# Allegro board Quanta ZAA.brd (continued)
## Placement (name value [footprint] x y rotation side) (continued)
Q4301  ev@me2n7002dkw-g_115ma  [SC70-2_1-65-6P]  170 113.64 0 top
Q4302  ev@me2n7002dkw-g_115ma  [SC70-2_1-65-6P]  184.97 108.35 180 bottom
Q6059  *2n7002k  [SOT23_213-3_3-2]  149.82 73.78 270 top
Q6060  2n7002k  [SOT23_213-3_3-2]  146.06 73.78 270 top
Q6062  typec@aon7401  [POWER-3_3X3_3-65-5P-SMT]  22.28 111.27 180 top
R1  *short_4  [S0402]  127.95 174.64 315 bottom
R2  *short_4  [S0402]  127.31 174.01 315 bottom
R3  *short_4  [S0402]  126.17 176.42 135 top
R4  *short_4  [S0402]  125.41 175.66 135 top
R5  *tsi@0_4  [R0402]  124.39 178.45 135 top
R6  *tsi@0_4  [R0402]  123.63 177.69 135 top
R7  *tsi@10k_4  [R0402]  134.04 180.61 180 bottom
R8  *tsi@0_4  [R0402]  132.77 180.41 270 bottom
R9  *tsi@10k_4  [R0402]  116.95 175.53 90 top
R10  *tsi@0_4  [R0402]  119.56 177.18 180 top
R11  *short_6  [S0603]  115.5 168.68 90 top
R12  *tsi@10k_4  [R0402]  122.1 175.41 270 top
R13  *tsi@0_4  [R0402]  119.44 173.63 0 top
R14  *short_8  [S0805]  115.7 163.49 270 bottom
R15  *short_8  [S0805]  113.8 162.35 270 bottom
R16  *short_6  [S0603]  115.37 170.71 180 top
R19  *0_4  [R0402]  117.15 170.45 270 top
R28  *short_8  [S0805]  114.43 162.17 270 top
R37  *short_4  [S0402]  113.34 157.25 270 bottom
R38  100k_4  [R0402]  113.72 158.52 0 bottom
R52  10k_4  [R0402]  114.1 151.91 0 top
R53  *100k_4  [R0402]  112.58 152.29 270 top
R58  10k_4  [R0402]  110.8 156.36 0 top
R65  100k_4  [R0402]  114.87 157.75 90 top
R66  *short_4  [S0402]  113.09 157.75 90 top
R67  *short_4  [S0402]  113.98 157.88 90 top
R74  1k_4  [R0402]  98.84 136.65 180 bottom
R85  1k_4  [R0402]  85.53 121.94 90 bottom
R89  60.4/f_4  [R0402]  94.54 126.64 0 bottom
R96  100/f_4  [R0402]  122.05 120.54 180 top
R98  100/f_4  [R0402]  122.23 122.4 270 top
R102  *short_4  [S0402]  90.73 121.94 90 bottom
R103  *0_4  [R0402]  91.75 121.94 90 bottom
R109  100/f_4  [R0402]  132.01 128.16 135 top
R110  *ev@10k_4  [R0402]  154.9 104.08 180 top
R112  *short_6  [S0603]  134.78 129.61 90 bottom
R113  *0_4  [R0402]  185.45 35.4 270 top
R115  iv@1k_4  [R0402]  159.39 105.89 0 top
R119  *short_4  [S0402]  225.48 140.48 90 bottom
R122  100/f_4  [R0402]  130.74 129.43 135 top
R127  ev@100k_4  [R0402]  161.09 105.89 0 top
R130  *10k_4  [R0402]  185.45 37.1 90 top
R131  *0_4  [R0402]  148.27 123.97 180 bottom
R134  54.9/f_4  [R0402]  95.18 131.84 90 bottom
R135  *short_6  [S0603]  133.48 126.18 0 top
R138  100/f_4  [R0402]  94.54 128.67 180 bottom
R145  100/f_4  [R0402]  136.15 124.73 90 top
R148  bl@10k_4  [R0402]  227.13 127.15 0 bottom
R152  2.2k_4  [R0402]  152.33 118.79 180 top
R153  1.5k/f_4  [R0402]  137.68 122.83 180 top
R154  24.9/f_4  [R0402]  118.59 120.6 180 top
R155  100/f_4  [R0402]  95.18 121.18 180 bottom
R156  49.9/f_4  [R0402]  97.85 124.35 180 top
R158  49.9/f_4  [R0402]  102.04 120.03 90 top
R160  *10k_4  [R0402]  140.52 114.8 180 top
R161  100/f_4  [R0402]  96.7 121.56 270 bottom
R162  49.9/f_4  [R0402]  103.03 120.44 90 top
R164  *short_4  [S0402]  151.77 112.8 270 bottom
R165  *2.2k_4  [R0402]  143.39 116.38 180 top
R166  2.2k_4  [R0402]  146.23 114.83 0 top
R167  2.2k_4  [R0402]  146.23 113.94 0 top
R169  *2.2k_4  [R0402]  143.39 115.49 180 top
R171  *short_4  [S0402]  146.36 114.24 0 bottom
R172  gt3@100/f_4  [R0402]  76.51 103.78 180 bottom
R174  200/f_4  [R0402]  143.95 113.94 0 top
R175  *short_4  [S0402]  146.36 115.11 0 bottom
R176  gt3@100/f_4  [R0402]  76.76 108 180 bottom
R177  10k_4  [R0402]  151.42 114.45 270 bottom
R178  113/f_4  [R0402]  141.15 112.97 0 top
R179  *short_6  [S0603]  151.06 112.29 270 top
R180  *short_6  [S0603]  149.03 115.21 180 top
R182  *short_6  [S0603]  149.03 113.68 180 top
R185  *short_6  [S0603]  155.25 112.29 270 top
R186  *short_6  [S0603]  152.46 112.29 270 top
R187  *short_6  [S0603]  148.65 112.26 180 top
R188  *short_6  [S0603]  153.85 112.29 270 top
R190  33_4  [R0402]  171.02 45.59 270 bottom
R192  *short_6  [S0603]  149.15 109.24 180 top
R193  *short_6  [S0603]  146.59 110.33 0 top
R194  *short_4  [S0402]  115.93 108.22 270 top
R195  *1k_4  [R0402]  157.89 112.14 90 top
R198  *short_6  [S0603]  156.65 112.29 270 top
R199  *gc6@10k_4  [R0402]  153.17 105.43 90 top
R203  *typec@0_4  [R0402]  29.01 124.61 90 top
R204  *gc6@10k_4  [R0402]  153.12 104.08 180 top
R205  *150k_4  [R0402]  159.44 102.25 180 top
R206  *typec@0_4  [R0402]  31.68 124.61 90 top
R207  *1k_4  [R0402]  159.44 103.14 0 top
R208  ev@10k_4  [R0402]  159.44 104.16 180 top
R209  *ioac@10k_4  [R0402]  230.31 106.57 90 top
R210  *0_6  [R0603]  165.28 74.39 180 top
R211  10k_4  [R0402]  160.84 98.95 0 top
R212  0_6  [R0603]  165.28 73.02 180 top
R213  75/f_4  [R0402]  19.11 67.33 0 top
R214  100k_4  [R0402]  162.62 88.03 0 bottom
R215  10k_4  [R0402]  153.6 95.9 180 top
R216  *ioac@10k_4  [R0402]  230.31 104.54 270 top
R217  *ioac@33_4  [R0402]  228.28 104.54 270 top
R218  *10k_4  [R0402]  66.16 115.19 180 bottom
R219  75/f_4  [R0402]  19.08 66.34 0 top
R221  *short_8  [S0805]  201.89 188.79 0 bottom
R222  75/f_4  [R0402]  19.08 65.25 0 top
R223  10k_4  [R0402]  153.6 93.87 180 top
R224  *short_4  [S0402]  153.6 92.86 0 top
R227  *10k_4  [R0402]  153.6 91.84 180 top
R228  10k_4  [R0402]  151.69 90.7 0 top
R229  *short_4  [S0402]  153.6 90.7 0 top
R230  *ioac@10k_4  [R0402]  203.89 191.15 0 top
R231  *ioac@100k_4  [R0402]  205.8 191.15 0 top
R234  ev@10k_4  [R0402]  151.69 89.55 0 top
R235  *short_4  [S0402]  153.6 89.55 0 top
R237  *short_8  [S0805]  201.86 191.66 180 bottom
R239  15_4  [R0402]  178.09 50.52 180 top
R240  *short_6  [S0603]  163.12 72.71 90 top
R241  *10k_4  [R0402]  177.73 176.42 180 top
R242  4.7k_4  [R0402]  179.51 176.42 0 top
R243  *0_4  [R0402]  179.89 178.3 90 top
R244  *0_4  [R0402]  179.2 174.64 0 bottom
R245  4.7k_4  [R0402]  178.11 179.72 180 top
R246  *short_8  [S0805]  44.41 67.91 180 top
R247  nac@2.2_8  [R0805]  45.45 64.04 180 top
R248  *ioac@0_8  [R0805]  44.7 65.97 0 top
R249  1m_4  [R0402]  129.85 74.19 90 top
R250  10k_4  [R0402]  137.85 95.27 270 bottom
R251  75/f_8  [R0805]  24.44 88.03 0 top
R252  *short_6  [S0603]  128.71 74.57 90 top
R253  *0_4  [R0402]  177.73 177.82 270 top
R254  *typec@0_4  [R0402]  29.9 114.19 270 top
R255  10m_4  [R0402]  153.47 106.7 90 bottom
R256  *ev@100k_4  [R0402]  156.6 72.97 90 top
R257  *ev@10k_4  [R0402]  155.99 75.18 90 top
R258  *typec@0_4  [R0402]  33.46 114.19 270 top
R259  *ioac@10k_4  [R0402]  50.68 70.38 90 top
R260  *ioac@100k/j_4  [R0402]  49.79 70.38 270 top
R262  75/f_8  [R0805]  24.44 82.32 0 top
R265  *0_4  [R0402]  171.96 90.57 90 bottom
R267  *0_4  [R0402]  173.16 98.44 270 top
R268  *0_4  [R0402]  170.95 90.57 90 bottom
R269  75/f_8  [R0805]  24.44 79.27 0 top
R270  *0_4  [R0402]  204.54 48 180 bottom
R271  *0_6  [R0603]  171.38 98.83 270 top
R272  *0_6  [R0603]  169.22 98.19 0 top
R273  *0_4  [R0402]  169.7 90.6 90 bottom
R274  *0_4  [R0402]  167.67 90.6 90 bottom
R275  *49.9k/f_4  [R0402]  148.52 112.16 270 bottom
R276  *0/j_4  [R0402]  33.2 64.15 90 top
R277  10k/f_4  [R0402]  32.19 64.15 270 top
R278  *0_6  [R0603]  169.22 99.59 180 top
R279  *0_4  [R0402]  168.69 90.6 90 bottom
R280  *49.9k/f_4  [R0402]  146.87 112.16 270 bottom
R281  *10k/f_4  [R0402]  35.87 60.85 270 top
R282  *0_4  [R0402]  166.07 91.43 90 bottom
R283  *49.9k/f_4  [R0402]  149.54 112.16 270 bottom
R289  *0_6  [R0603]  167.82 101.11 0 top
R290  *49.9k/f_4  [R0402]  145.88 112.16 270 bottom
R291  *0_6  [R0603]  166.93 98.95 270 top
R299  20k/f_4  [R0402]  77.4 49.3 180 top
R300  20k/f_4  [R0402]  77.4 50.18 180 top
R301  45.3k/f_4  [R0402]  77.4 51.2 180 top
R303  *120/f_4  [R0402]  14.53 50.82 270 top
R304  1.5k/f_4  [R0402]  79.3 51.2 180 top
R308  1k_4  [R0402]  72.83 51.33 90 top
R312  *120/f_4  [R0402]  14.53 45.49 270 top
R314  *120/f_4  [R0402]  14.53 47.26 270 top
R315  *120/f_4  [R0402]  14.53 49.04 270 top
R316  2.2k_4  [R0402]  17.96 43.33 270 top
R317  2.2k_4  [R0402]  18.98 43.33 270 top
R318  *short_6  [S0603]  218.22 63.01 180 bottom
R319  2.2k_4  [R0402]  18.45 53.36 270 top
R322  2.2k_4  [R0402]  17.48 53.36 270 top
R326  *0_4  [R0402]  224.59 53.87 270 bottom
R329  *short_4  [S0402]  224.8 60.85 0 bottom
R333  *gs@4.7k_4  [R0402]  222.18 62.5 270 bottom
R334  *gs@4.7k_4  [R0402]  224.92 58.95 180 bottom
R336  *short_4  [S0402]  224.8 59.96 0 bottom
R337  *short_4  [S0402]  224.92 57.04 0 bottom
R338  *short_6  [S0603]  213.92 43.94 90 bottom
R339  *short_8  [S0805]  220.35 45.33 90 bottom
R340  *short_4  [S0402]  21.67 34.59 180 top
R341  *short_4  [S0402]  21.67 33.57 180 top
R342  *short_4  [S0402]  21.65 32.4 180 top
R343  *100k_4  [R0402]  205.85 44.17 270 bottom
R344  *0_4  [R0402]  203.51 40.28 270 bottom
R345  *1m_6  [R0603]  207.83 45.69 90 bottom
R348  *short_4  [S0402]  21.65 31.52 180 top
R349  33_4  [R0402]  189.08 44.39 270 bottom
R350  *short_4  [S0402]  203.51 38.12 90 bottom
R351  *0_4  [R0402]  224.08 40.41 180 bottom
R352  22k_4  [R0402]  208.59 39.9 270 bottom
R353  *short_4  [S0402]  21.65 30.37 180 top
R354  10k_4  [R0402]  207.63 38.12 270 bottom
R355  *short_4  [S0402]  21.65 29.48 180 top
R356  10k_4  [R0402]  16.95 22.5 270 top
R359  33_4  [R0402]  205.54 38.12 270 bottom
R360  10k_4  [R0402]  16.06 22.5 270 top
R361  *2.2_6  [R0603]  190.02 41.55 0 bottom
R364  100k_4  [R0402]  16.34 29.18 270 top
R365  *short_4  [S0402]  207.55 37.66 0 top
R366  *0_4  [R0402]  205.87 37.94 270 top
R367  *short_6  [S0603]  200.72 40.53 270 bottom
R368  100k_4  [R0402]  191.32 35.45 270 bottom
R369  *10k_4  [R0402]  198.05 40.81 90 bottom
R370  22_4  [R0402]  202.49 38.12 90 bottom
R371  *short_4  [S0402]  201.61 38.12 90 bottom
R372  1k_4  [R0402]  198.94 40.81 270 bottom
R373  *22_4  [R0402]  189.79 36.98 0 bottom
R374  10k_4  [R0402]  155.89 24.28 0 bottom
R375  *0_4  [R0402]  208.51 36.16 270 top
R376  39k/f_4  [R0402]  21.98 27.71 90 top
R377  20k/f_4  [R0402]  20.96 27.71 270 top
R378  100k_4  [R0402]  209.51 36.16 90 bottom
R380  100k_4  [R0402]  189.79 35 180 bottom
R381  *short_4  [S0402]  18.34 18.43 270 top
R382  ev@10k_4  [R0402]  169.09 29.86 0 bottom
R383  200k_4  [R0402]  209.99 34.74 0 bottom
R384  *short_4  [S0402]  19.36 18.43 270 top
R385  *short_4  [S0402]  19.87 13.86 180 top
R386  *short_4  [S0402]  19.87 13 180 top
R387  *short_4  [S0402]  19.23 10.56 90 top
R388  *short_6  [S0603]  211.51 30.88 0 top
R389  100k_4  [R0402]  189.79 29.86 180 bottom
R390  *10k/f_4  [R0402]  208.84 21.04 0 bottom
R392  *short_4  [S0402]  18.34 10.56 90 top
R393  *0_4  [R0402]  208.51 36.16 270 bottom
R394  *0_4  [R0402]  211.51 33.19 180 top
R395  *29.4k/f_4  [R0402]  208.84 22.02 0 bottom
R397  100k_4  [R0402]  208.57 28.39 0 bottom
R399  *0_4  [R0402]  209.23 26.18 180 bottom
R400  *0_4  [R0402]  206.84 31.34 0 top
R401  *0_4  [R0402]  210.32 28.75 0 bottom
R402  *short_4  [S0402]  121.79 23.16 270 bottom
R403  *short_4  [S0402]  137.85 16.53 0 bottom
R404  *short_6  [S0603]  72.95 15.13 90 top
R405  *short_4  [S0402]  141.38 15.08 0 bottom
R406  *short_6  [S0603]  74.22 15.13 90 top
R407  2.2k_4  [R0402]  205.49 15.13 180 bottom
R408  *short_4  [S0402]  207.32 15.13 180 bottom
R409  *2.2k_4  [R0402]  141.38 14.14 180 bottom
R410  *2.2k_4  [R0402]  136.07 16.78 0 bottom
R411  *short_4  [S0402]  119.66 21.36 90 bottom
R412  *short_4  [S0402]  120.93 21.36 90 bottom
R414  *short_6  [S0603]  75.49 15.13 90 top
R415  10k_4  [R0402]  119.63 23.16 90 bottom
R416  10k_4  [R0402]  120.9 23.16 90 bottom
R417  *10k_4  [R0402]  205.37 10.59 0 bottom
R418  4.7k_4  [R0402]  204.5 19.22 270 bottom
R419  *short_6  [S0603]  76.76 15.13 90 top
R420  62/f_4  [R0402]  207.07 10.59 0 bottom
R421  4.7k_4  [R0402]  208.39 18.56 270 bottom
R422  62/f_4  [R0402]  207.07 11.7 0 bottom
R423  *10k_4  [R0402]  205.37 11.7 0 bottom
R424  2.2k_4  [R0402]  205.49 13.61 180 bottom
R425  *short_4  [S0402]  207.32 13.61 180 bottom
R426  *1m_4  [R0402]  53.04 20.75 270 top
R427  *1m_4  [R0402]  55.2 20.75 270 top
R428  *1m_4  [R0402]  58.62 20.73 270 top
R429  *1m_4  [R0402]  59.72 20.73 270 top
R430  47/f_4  [R0402]  58.62 18.83 90 top
R431  124/f_4  [R0402]  59.72 18.83 90 top
R432  47/f_4  [R0402]  54.1 18.84 90 top
R433  124/f_4  [R0402]  55.2 18.84 90 top
R435  *100k_4  [R0402]  79.69 9.77 270 top
R436  *1m_4  [R0402]  54.1 20.75 270 top
R437  *short_4  [S0402]  57.53 18.95 270 top
R438  *short_4  [S0402]  53.04 18.84 270 top
R439  *0_4  [R0402]  57.53 17.05 90 top
R440  *0_4  [R0402]  53.04 17.06 90 top
R441  33_4  [R0402]  131.88 178.84 0 bottom
R442  *short_4  [S0402]  128.2 178.84 0 top
R443  *tsi@0_4  [R0402]  131.76 180.41 270 bottom
R444  *tsi@10k_4  [R0402]  121.09 168.55 90 bottom
R447  *100k_4  [R0402]  122.79 169.91 0 bottom
R448  *100k_4  [R0402]  122.76 168.9 180 bottom
R449  *100k_4  [R0402]  124.52 168.93 0 bottom
R450  *100k_4  [R0402]  124.52 169.95 180 bottom
R457  33_4  [R0402]  121.85 171.85 0 top
R460  33_4  [R0402]  182.63 47.82 270 bottom
R463  100k_4  [R0402]  169.09 30.75 0 bottom
R465  1k_4  [R0402]  94.54 125.62 0 bottom
R478  *0_4  [R0402]  99.35 138.42 90 bottom
R485  10k_4  [R0402]  98.41 138.42 90 bottom
R488  *1k_4  [R0402]  98.99 134.11 0 bottom
R512  2.7k/f_4  [R0402]  118.27 127.4 270 bottom
R513  *1k_4  [R0402]  101.28 131.85 270 bottom
R514  51_4  [R0402]  103.46 131.85 90 bottom
R515  51_4  [R0402]  104.48 131.85 90 bottom
R529  1k_4  [R0402]  99.24 131.85 90 bottom
R530  100/f_4  [R0402]  100.26 129.81 90 bottom
R531  499/f_4  [R0402]  96.32 125.62 180 bottom
R532  *100k_4  [R0402]  96.95 129.43 0 bottom
R533  *100k_4  [R0402]  98.85 129.43 0 bottom
R534  51_4  [R0402]  105.34 129.81 90 bottom
R536  1m_4  [R0402]  117.79 130.83 180 bottom
R537  *51_4  [R0402]  106.99 129.81 90 bottom
R540  10k_4  [R0402]  147.76 125.11 180 bottom
R541  10k_4  [R0402]  147.76 127.02 180 bottom
R542  10k_4  [R0402]  147.76 126 180 bottom
R543  10k_4  [R0402]  147.76 127.91 180 bottom
R544  *10k_4  [R0402]  95.31 124.61 180 bottom
R546  *0_4  [R0402]  108.9 131.46 90 bottom
R548  1k_4  [R0402]  95.43 123.72 180 bottom
R550  *short_6  [S0603]  134.04 129 0 top
R552  220_4  [R0402]  95.18 130.08 270 bottom
R553  *0_4  [R0402]  109.78 131.46 90 bottom
R554  10k_4  [R0402]  96.83 124.23 90 bottom
R555  10k_4  [R0402]  146.36 123.97 180 bottom
R556  *short_4  [S0402]  148.27 122.96 0 bottom
R558  51_4  [R0402]  101.28 129.81 90 bottom
R559  51_4  [R0402]  102.29 131.85 90 bottom
R560  *short_4  [S0402]  181.57 37.87 180 top
R561  10k_4  [R0402]  145.85 122.7 0 bottom
R562  100/f_4  [R0402]  138.39 121.32 90 top
R563  100k_4  [R0402]  147.73 120.59 270 top
R564  100k_4  [R0402]  145.47 118.89 180 top
R565  gt3@0_6  [R0603]  90.65 125.16 270 bottom
R568  10k_4  [R0402]  149.13 121.79 0 bottom
R569  *10k_4  [R0402]  147.55 120.16 180 bottom
R570  100k_4  [R0402]  149.97 119.83 270 bottom
R571  *short_4  [S0402]  150.55 119.65 0 top
R572  2.2k_4  [R0402]  157.92 116.61 270 top
R573  *10k_4  [R0402]  144.71 120.16 180 bottom
R574  *10k_4  [R0402]  144.71 119.15 180 bottom
R575  *10k_4  [R0402]  146.61 119.15 0 bottom
R576  2.2k_4  [R0402]  157.92 118.76 90 top
R577  *2.2k_4  [R0402]  152.33 117.49 180 top
R578  2.2k_4  [R0402]  140.52 115.64 0 top
R580  2.2k_4  [R0402]  140.52 116.66 0 top
R582  2.2k_4  [R0402]  150.53 117.42 180 top
R585  2.2k_4  [R0402]  149.71 114.45 90 bottom
R586  *1k_4  [R0402]  150.55 114.45 90 bottom
R587  1k_4  [R0402]  144.58 109.8 0 bottom
R588  15_4  [R0402]  179.51 56.79 270 top
R589  15_4  [R0402]  180.9 58.57 90 top
R590  *tpm@10k_4  [R0402]  148.52 105.56 180 bottom
R591  10k_4  [R0402]  178.24 56.79 270 top
R592  10k_4  [R0402]  146.79 105.56 180 bottom
R593  10k_4  [R0402]  152.58 107.97 180 top
R595  10k_4  [R0402]  148.65 104.92 0 top
R598  nac@10k_4  [R0402]  148.65 105.94 0 top
R599  *ioac@10k_4  [R0402]  150.68 105.94 180 top
R600  *10k_4  [R0402]  150.68 104.92 180 top
R601  2.2k_4  [R0402]  13.14 81.91 180 bottom
R602  *short_4  [S0402]  178.24 58.54 270 top
R605  10k_4  [R0402]  150.68 105.05 180 bottom
R606  *10k_4  [R0402]  148.65 107.97 180 top
R607  10k_4  [R0402]  150.42 107.97 180 top
R608  *gs@10k_4  [R0402]  152.58 105.05 180 bottom
R609  10k_4  [R0402]  66.9 120.08 0 bottom
R610  *10k_4  [R0402]  147 102.89 180 bottom
R611  *10k_4  [R0402]  148.9 102.89 180 bottom
R612  *10k_4  [R0402]  147 103.86 180 bottom
R613  *10k_4  [R0402]  148.9 103.91 180 bottom
R614  *10k_4  [R0402]  150.55 102.38 270 bottom
R615  *10k_4  [R0402]  152.08 102.76 180 bottom
R616  200/f_4  [R0402]  148.9 101.87 0 bottom
R617  *typec@4.7k/f_4  [R0402]  27.79 121.98 0 bottom
R618  *10k_4  [R0402]  152.08 100.35 180 bottom
R619  *1k_4  [R0402]  152.08 101.75 0 bottom
R620  2.2k_4  [R0402]  12.76 76.6 180 bottom
R621  *10k_4  [R0402]  95.05 101.87 90 bottom
R623  22_4  [R0402]  152.08 98.17 0 bottom
R624  *20k_4  [R0402]  150.17 100.35 0 bottom
R625  *1k_4  [R0402]  152.08 99.33 0 bottom
R626  22_4  [R0402]  152.08 95.78 270 bottom
R627  22_4  [R0402]  152.58 97.17 0 bottom
R628  8.2k/f_4  [R0402]  160.64 72.46 270 top
R629  10k_4  [R0402]  153.22 90.32 270 bottom
R630  8.2k/f_4  [R0402]  142.55 97.68 0 bottom
R631  *10k_4  [R0402]  152.2 90.32 90 bottom
R632  gt3@0_4  [R0402]  78.42 106.45 180 bottom
R633  gt3@0_4  [R0402]  78.42 105.05 180 bottom
R634  gt3@0_4  [R0402]  76.51 105.05 0 bottom
R635  49.9/f_4  [R0402]  158.88 73.58 270 top
R636  gt3@0_4  [R0402]  76.51 106.45 0 bottom
R639  10k_4  [R0402]  139.5 95.4 270 bottom
R640  *short_4  [S0402]  139.86 97.17 0 bottom
R642  10k_4  [R0402]  134.93 93.24 90 bottom
R643  *0_4  [R0402]  132.9 95.14 270 bottom
R644  33_4  [R0402]  129.6 95.14 270 bottom
R645  33_4  [R0402]  130.61 93.24 270 bottom
R646  49.9/f_4  [R0402]  157.92 73.56 270 top
R647  *short_4  [S0402]  133.91 95.14 90 bottom
R648  10k_4  [R0402]  133.91 93.24 90 bottom
R649  1k_4  [R0402]  180.9 56.79 270 top
R650  15_4  [R0402]  179.51 58.57 90 top
R651  8.2k/f_4  [R0402]  136.84 95.27 90 bottom
R652  *short_4  [S0402]  139.5 93.24 270 bottom
R653  *short_4  [S0402]  141.15 93.24 270 bottom
R654  15_4  [R0402]  182.17 51.96 90 top
R655  *short_4  [S0402]  135.82 93.24 270 bottom
R657  *short_8  [S0805]  225.56 105.23 0 bottom
R659  *short_4  [S0402]  140.52 95.4 270 bottom
R660  33_4  [R0402]  132.26 93.24 270 bottom
R661  *short_4  [S0402]  135.06 95.14 270 bottom
R667  33_4  [R0402]  131.63 95.14 270 bottom
R668  *short_4  [S0402]  141.66 95.4 270 bottom
R670  *short_4  [S0402]  130.89 100.65 180 top
R671  nac@0_4  [R0402]  201.1 181.12 0 bottom
R672  nac@0_8  [R0805]  226.22 102.69 90 bottom
R673  *ioac@22_8  [R0805]  222.81 105.04 270 bottom
R676  *short_4  [S0402]  137.34 93.24 270 bottom
R677  *short_4  [S0402]  138.49 93.24 270 bottom
R678  80.6/f_4  [R0402]  130.36 103.35 270 top
R679  470_4  [R0402]  130.89 101.65 180 top
R680  *ioac@0_4  [R0402]  201.1 180.11 0 bottom
R681  100/f_4  [R0402]  131.3 103.35 270 top
R682  *100k_4  [R0402]  89.59 102 270 bottom
R683  *0_6  [R0603]  154.16 73.76 180 top
R684  15_4  [R0402]  180.9 50.18 90 top
R685  121/f_4  [R0402]  130.49 106.14 90 top
R686  *ioac@100k  [R0402]  225.18 110.09 270 top
R687  15_4  [R0402]  180.9 51.96 90 top
R688  *short_4  [S0402]  201.07 177.03 0 bottom
R690  *short_4  [S0402]  201.07 176.09 0 bottom
R691  15_4  [R0402]  183.5 51.96 270 top
R692  *ioac@100k  [R0402]  225.23 107.08 180 top
R693  *short_4  [S0402]  201.07 175.15 0 bottom
R694  *0_4  [R0402]  201.05 172.82 180 bottom
R695  *ioac@100k  [R0402]  227.77 108.48 90 bottom
R696  *short_4  [S0402]  201.07 174.19 0 bottom
R697  *gt3@10k_4  [R0402]  48.44 83.46 0 top
R698  1k_4  [R0402]  179.89 51.96 270 top
R699  *0_4  [R0402]  201.05 171.83 180 bottom
R702  *ioac@1k_4  [R0402]  43.24 80.92 90 top
R703  *ioac@0_4  [R0402]  225.23 104.92 180 top
R704  *ioac@0_4  [R0402]  225.23 105.94 180 top
R705  gt3@10k_4  [R0402]  48.44 81.55 0 top
R706  *gt3@10k_4  [R0402]  48.42 81.55 180 bottom
R707  gt3@10k_4  [R0402]  48.42 82.44 180 bottom
R708  *gt3@10k_4  [R0402]  48.44 82.44 0 top
R709  nac@0/j_4  [R0402]  43.24 79.01 90 top
R710  *ioac@10k_4  [R0402]  205.8 189.22 180 top
R712  *ioac@100k_4  [R0402]  203.89 189.22 180 top
R713  nac@0_4  [R0402]  46.97 77.26 90 top
R714  *10k_4  [R0402]  201.1 182.14 180 bottom
R715  *ioac@0_4  [R0402]  46.11 77.26 90 top
R716  *10k_4  [R0402]  202.49 185.57 180 bottom
R717  *10k_4  [R0402]  218.88 72.54 270 top
R718  *short_4  [S0402]  26.09 53.87 270 top
R719  100k_4  [R0402]  219.51 69.11 0 top
R720  20k_4  [R0402]  15.68 58.44 0 top
R721  *short_4  [S0402]  15.68 57.17 0 top
R722  *1m_4  [R0402]  26.98 53.87 270 top
R725  *short_6  [S0603]  168.51 65.12 180 bottom
R729  *tpm@10k_4  [R0402]  166.55 67.33 270 bottom
R730  10k_4  [R0402]  177.32 47.87 90 bottom
R731  4.7k_4  [R0402]  178.26 45.64 270 bottom
R732  4.7k_4  [R0402]  179.2 45.64 270 bottom
R733  2.2k_4  [R0402]  181.16 45.61 270 bottom
R734  2.2k_4  [R0402]  182.17 45.61 270 bottom
R735  *10k_4  [R0402]  173.92 45.61 270 bottom
R736  *10k_4  [R0402]  173.92 47.87 90 bottom
R737  1k_4  [R0402]  130.61 95.14 270 bottom
R738  43_4  [R0402]  180.3 48.15 180 bottom
R739  100k_4  [R0402]  181.79 47.82 270 bottom
R740  ev@10k_4  [R0402]  167.19 29.89 180 bottom
R741  10k_4  [R0402]  172.22 48 270 bottom
R742  *short_4  [S0402]  164.14 76.7 90 bottom
R743  *short_4  [S0402]  162.03 72.08 90 bottom
R744  *tpm@4.7k_4  [R0402]  170.21 72.46 0 bottom
R745  *short_6  [S0603]  163.25 66.57 270 bottom
R746  33_4  [R0402]  170.9 42.92 90 bottom
R747  2.2_6  [R0603]  187.89 47.44 0 bottom
R749  *short_4  [S0402]  189.79 33.93 180 bottom
R750  *short_4  [S0402]  209.33 24.58 180 bottom
R751  33_4  [R0402]  190.58 27.99 0 bottom
R752  0_6  [R0603]  130.45 14.62 270 bottom
R753  *10k_4  [R0402]  217.1 37.13 270 bottom
R754  *0_4  [R0402]  130.99 16.91 90 bottom
R756  *0_4  [R0402]  219.89 70.76 90 top
R757  *0_4  [R0402]  218.88 70.76 90 top
R759  *short_4  [S0402]  148.88 101.87 180 top
R760  *short_4  [S0402]  93.15 100.35 0 bottom
R761  100k_4  [R0402]  94.54 127.65 0 bottom
R762  gt3@0_4  [R0402]  78.42 103.78 0 bottom
R764  10k_4  [R0402]  148.65 106.95 180 top
R765  *10k_4  [R0402]  150.68 106.95 180 top
R766  ev_sp@10k_4  [R0402]  150.68 104.16 180 bottom
R767  ev_a@10k_4  [R0402]  152.58 104.16 180 bottom
R774  33_4  [R0402]  171.63 27.2 90 bottom
R775  *0_4  [R0402]  151.06 115.11 180 top
R776  for15@33_4  [R0402]  150.55 19.58 270 bottom
R777  *0_4  [R0402]  89.72 121.94 270 bottom
R778  1k_4  [R0402]  142.42 110.38 180 top
R779  2.2_6  [R0603]  190.02 40.15 0 bottom
R781  20k/f_4  [R0402]  152.33 119.78 180 top
R782  *short_4  [S0402]  189.79 30.88 180 bottom
R783  *0_4  [R0402]  168.92 35.3 90 bottom
R784  *0_4  [R0402]  189.97 43.68 270 bottom
R785  *0_4  [R0402]  175.11 45.61 270 bottom
R786  100k_4  [R0402]  152.25 72.84 90 top
R788  49.9/f_4  [R0402]  100.26 131.85 90 bottom
R789  *short_6  [S0603]  154.16 75.2 0 top
R790  *short_4  [S0402]  172.47 52.39 90 bottom
R791  *short_4  [S0402]  189.01 27.4 270 bottom
R792  *short_4  [S0402]  160.08 32.02 90 bottom
R795  *short_4  [S0402]  102.29 129.81 90 bottom
R796  *short_4  [S0402]  104.32 129.81 90 bottom
R797  *short_4  [S0402]  103.31 129.81 90 bottom
R816  *short_4  [S0402]  18.22 123.46 0 bottom
R817  *short_4  [S0402]  18.22 122.7 0 bottom
R818  *short_4  [S0402]  19.21 118.66 0 top
R819  *short_4  [S0402]  19.21 119.48 0 top
R820  *short_4  [S0402]  16.34 117.6 0 bottom
R821  *short_4  [S0402]  16.34 116.71 0 bottom
R856  ev@10k_4  [R0402]  198.43 109.88 180 bottom
R857  *ev@0_4  [R0402]  197.29 111.78 90 bottom
R858  *ev@0_4  [R0402]  196.27 111.78 90 bottom
R859  ev@40.2/f_4  [R0402]  188.4 140.1 180 top
R860  ev@40.2/f_4  [R0402]  190.25 140.1 0 top
R861  ev@60.4/f_4  [R0402]  189.92 137.18 270 top
R866  *fpd@0_4  [R0402]  111.31 35.2 90 top
R948  *short_8  [S0805]  179.71 88.72 90 bottom
R956  *short_4  [S0402]  166.43 93.36 90 bottom
R957  *10k_4  [R0402]  165.41 93.36 270 bottom
R958  *short_4  [S0402]  167.95 105.81 270 bottom
R959  *short_4  [S0402]  166.93 105.81 270 bottom
R960  *short_4  [S0402]  163.51 91.16 0 bottom
R961  1m_4  [R0402]  171.25 106.06 270 bottom
R968  *0_4  [R0402]  170.24 106.06 90 bottom
R1297  ev_b@931/f_4  [R0402]  215.58 153.82 90 bottom
R1308  ev_b@10k_4  [R0402]  213.49 129.76 180 top
R1309  ev_b@10k_4  [R0402]  214.94 138.83 90 top
R1318  ev_b@10k_4  [R0402]  211.64 129.76 0 top
R1319  ev_b@10k_4  [R0402]  211.89 137.56 90 top
R1323  ev_b@1k_4  [R0402]  213.8 122.32 0 top
R1330  ev_b@931/f_4  [R0402]  216.97 112.41 270 bottom
R1331  ev_b@549/f_4  [R0402]  215.83 112.41 270 bottom
R1333  ev_b@120/f_4  [R0402]  211.51 153.82 90 bottom
R1335  ev_b@120/f_4  [R0402]  212.4 112.41 270 bottom
R1336  ev_b@80.6/f_4  [R0402]  212.38 121.41 0 top
R1337  ev_b@1.33k/f_4  [R0402]  214.69 112.41 270 bottom
R1342  ev_b@80.6/f_4  [R0402]  212.93 149.78 180 top
R1367  ev_b@1.33k/f_4  [R0402]  213.67 153.82 90 bottom
R1381  ev_b@549/f_4  [R0402]  214.56 153.82 90 bottom
R1410  ev_a@931/f_4  [R0402]  206.43 164.1 90 bottom
R1415  ev_a@120/f_4  [R0402]  205.54 160.42 0 bottom
R1416  ev_a@1.33k/f_4  [R0402]  205.54 162.45 0 bottom
R1417  ev_a@549/f_4  [R0402]  205.37 164.1 90 bottom
R1426  ev_a@80.6/f_4  [R0402]  195.89 160.8 90 top
R1438  ev_a@1k_4  [R0402]  173.03 160.42 270 top
R1466  ev_a@10k_4  [R0402]  190.3 162.96 270 top
R1467  ev_a@10k_4  [R0402]  189.41 162.96 270 top
R1472  ev_a@10k_4  [R0402]  180.4 160.93 270 top
R1473  ev_a@10k_4  [R0402]  175.44 160.8 270 top
R1500  ev_a@80.6/f_4  [R0402]  169.35 161.31 270 top
R1508  ev_a@1.33k/f_4  [R0402]  165.16 162.96 180 top
R1509  ev_a@549/f_4  [R0402]  165.16 163.98 180 top
R1510  ev_a@120/f_4  [R0402]  165.16 160.93 180 top
R1513  ev_a@931/f_4  [R0402]  165.16 164.99 180 top
R2854  *fpd@10k_4  [R0402]  114.94 32.13 90 top
R2855  *short_4  [S0402]  112.83 18.94 90 bottom
R2868  fpd@10_4  [R0402]  112.83 22.88 0 bottom
R2870  *short_4  [S0402]  112.83 26.44 0 bottom
R2872  *short_4  [S0402]  112.83 21.99 0 bottom
R4000  gc6@10k_4  [R0402]  164.27 110.89 90 top
R4001  gc6@10k_4  [R0402]  164.03 108.56 90 top
R4002  gc6@100k_4  [R0402]  165.26 110.89 270 top
R4003  *gc6@0_8  [R0805]  173.34 108.3 90 top
R4004  *gc6@10k_4  [R0402]  220.54 107.96 270 bottom
R4005  gc6@100k_4  [R0402]  219.53 107.96 90 bottom
R4006  *ev@200/f_4  [R0402]  164.51 143.28 0 bottom
R4007  *gc6@0_4  [R0402]  217.1 108.58 0 bottom
R4008  ev@10k_4  [R0402]  170.88 126.77 180 top
R4009  ev@2.49k/f_4  [R0402]  164.53 144.29 180 bottom
R4010  *short_6  [S0603]  171.51 140.76 180 top
R4011  ev@10k_4  [R0402]  169.3 125.93 0 top
R4012  gc6@1m_4  [R0402]  229.55 115.34 180 bottom
R4100  *ev@60.4/f_4  [R0402]  192.46 127.53 0 top
R4102  *ev@60.4/f_4  [R0402]  192.59 134.89 0 top
R4103  *ev@60.4/f_4  [R0402]  184.71 143.53 90 top
R4105  *ev@60.4/f_4  [R0402]  178.11 145.94 0 top
R4200  ev@1.5k/f_4  [R0402]  177.73 110.51 270 bottom
R4201  ev@4.7k_4  [R0402]  176.21 108.6 270 bottom
R4202  *ev@100k/f_4  [R0402]  178.75 110.51 90 bottom
R4203  ev@4.7k_4  [R0402]  174.81 110.51 270 bottom
R4204  ev@4.7k_4  [R0402]  157.13 139.29 90 bottom
R4205  ev@4.7k_4  [R0402]  159.42 142.46 90 bottom
R4206  ev@100k/f_4  [R0402]  158.12 139.29 270 bottom
R4207  ev@4.7k_4  [R0402]  164.27 142.13 180 bottom
R4208  ev@1.8k/f_4  [R0402]  182.43 114.19 270 bottom
R4209  ev@1.8k/f_4  [R0402]  182.94 119.78 270 top
R4210  *ev@10k_4  [R0402]  187.89 109.75 270 top
R4211  ev@10k_4  [R0402]  187.89 111.78 90 top
R4212  ev@10k_4  [R0402]  191.12 111.78 270 bottom
R4300  ev@49.9k/f_4  [R0402]  192.24 109.71 90 bottom
R4301  *ev@45.3k/f_4  [R0402]  197.29 109.75 90 top
R4302  *ev@15k/f_4  [R0402]  196.27 109.75 90 top
R4303  *ev@34.8k/f_4  [R0402]  188.91 109.75 90 top
R4304  *ev@20k/f_4  [R0402]  188.91 109.75 90 bottom
R4305  ev_sp@xxxx  [R0402]  195.92 109.04 90 bottom
R4306  ev_sp@4.99k/f_4  [R0402]  198.3 109.75 90 top
R4307  *ev@10k/f_4  [R0402]  189.92 109.75 90 top
R4308  *ev@4.99k/f_4  [R0402]  191.27 109.71 270 bottom
R4309  *ev@4.99k/f_4  [R0402]  197.29 111.78 90 top
R4310  *ev@24.9k/f_4  [R0402]  196.27 111.78 90 top
R4311  *ev@4.99k/f_4  [R0402]  188.91 111.78 90 top
R4312  *ev@45.3k/f_4  [R0402]  188.91 111.78 90 bottom
R4313  ev_sp@xxxx  [R0402]  194.98 109.04 270 bottom
R4314  ev_sp@4.99k/f_4  [R0402]  198.3 111.78 90 top
R4315  ev@4.99k/f_4  [R0402]  189.92 111.78 90 top
R4316  ev@10k_4  [R0402]  186.49 114.19 270 bottom
R4317  ev@10k_4  [R0402]  185.48 114.19 270 bottom
R4318  ev@10k_4  [R0402]  183.44 114.32 90 top
R4319  ev@10k_4  [R0402]  166.6 114.09 0 top
R4320  *ev@10k_4  [R0402]  187 111.78 90 top
R4321  ev@10k_4  [R0402]  188.91 114.19 90 bottom
R4322  ev@10k_4  [R0402]  183.44 114.19 90 bottom
R4323  *ev@10k_4  [R0402]  187.38 111.14 0 bottom
R4324  ev@10k_4  [R0402]  183.44 112.16 90 top
R4325  ev@100k_4  [R0402]  187.38 112.16 0 bottom
R4326  ev@10k_4  [R0402]  189.62 105.25 180 bottom
R4328  *short_4  [S0402]  193.15 105.25 180 bottom
R4329  *short_4  [S0402]  191.37 105.25 180 bottom
R4330  *ev@10k_4  [R0402]  162.36 124.99 180 bottom
R4331  *ev@10k_4  [R0402]  162.36 126.26 180 bottom
R4332  *ev@10k_4  [R0402]  162.39 122.8 180 bottom
R4334  ev@10k_4  [R0402]  162.39 123.82 180 bottom
R4335  *short_4  [S0402]  189.01 107.16 0 bottom
R4336  *short_4  [S0402]  194.6 106.06 270 bottom
R4337  ev@1.8k/f_4  [R0402]  184.46 114.19 90 bottom
R4338  ev@1.8k/f_4  [R0402]  182.94 122.07 270 top
R4339  ev@1.8k/f_4  [R0402]  182.43 111.91 90 bottom
R4340  ev@1.8k/f_4  [R0402]  181.41 111.91 90 bottom
R4341  ev@2.2k_4  [R0402]  185.58 110.46 270 bottom
R4342  ev@2.2k_4  [R0402]  182.3 108.1 270 bottom
R4343  *ev@10k_4  [R0402]  187.89 114.19 90 bottom
R4344  *ev@10k_4  [R0402]  189.92 109.75 270 bottom
R4345  ev@40.2k/f_4  [R0402]  189.92 111.78 90 bottom
R4346  *ev@0_4  [R0402]  166.62 115.19 180 top
R10842  *short_4  [S0402]  113.09 127.79 270 bottom
R10843  *short_4  [S0402]  112.2 127.79 270 bottom
R10844  *short_4  [S0402]  110.04 127.79 270 bottom
R10845  *short_4  [S0402]  110.93 127.79 270 bottom
R10846  *short_4  [S0402]  147.26 118.89 180 top
R10847  *short_4  [S0402]  98.25 130.83 270 bottom
R10848  *short_4  [S0402]  97.24 130.83 270 bottom
R10871  240_4  [R0402]  102.04 51.58 90 top
R10872  *10k_4  [R0402]  145.85 39.16 90 bottom
R10873  24.9/f_4  [R0402]  128.2 40.2 90 top
R10875  240_4  [R0402]  104.45 47.14 180 top
R10877  10k_4  [R0402]  127.82 47.14 90 top
R10878  2/f_6  [R0603]  126.29 38.12 0 top
R10879  240_4  [R0402]  104.45 43.71 180 top
R10880  *10k_4  [R0402]  147 39.16 90 bottom
R10881  240_4  [R0402]  104.45 51.96 180 top
R10882  10k_4  [R0402]  145.85 37.38 90 bottom
R10883  1k/f_4  [R0402]  125.91 42.82 0 top
R10884  240_4  [R0402]  103.05 51.58 90 top
R10885  240_4  [R0402]  116.64 42.95 180 top
R10886  10k_4  [R0402]  147 37.38 90 bottom
R10887  *0_4  [R0402]  126.29 36.85 0 top
R10888  240_4  [R0402]  110.04 41.68 0 top
R10889  *10k_4  [R0402]  128.83 47.14 270 top
R10890  *1k_4  [R0402]  116.64 43.96 0 top
R10891  240_4  [R0402]  104.45 48.03 180 top
R10892  240_4  [R0402]  110.04 42.69 0 top
R10894  240_4  [R0402]  104.45 51.07 180 top
R10895  1k/f_4  [R0402]  126.17 39.39 180 top
R10896  240_4  [R0402]  104.45 46.12 180 top
R10921  *1k_4  [R0402]  114.69 44.85 90 top
R10922  240_4  [R0402]  104.2 59.2 180 top
R10923  *10k_4  [R0402]  126.55 62.38 270 top
R10924  *10k_4  [R0402]  148.77 57.86 270 top
R10925  240_4  [R0402]  109.91 58.57 0 top
R10926  240_4  [R0402]  104.2 63.77 180 top
R10927  10k_4  [R0402]  125.53 62.38 90 top
R10928  240_4  [R0402]  115.12 56.41 180 top
R10929  240_4  [R0402]  104.2 62.88 180 top
R10930  24.9/f_4  [R0402]  117.4 66.31 270 top
R10931  240_4  [R0402]  104.45 54.5 180 top
R10932  2/f_6  [R0603]  117.02 63.65 180 top
R10933  240_4  [R0402]  109.91 62.76 0 top
R10934  1k/f_4  [R0402]  117.15 62.38 180 top
R10935  *0_4  [R0402]  116.72 57.55 180 top
R10936  240_4  [R0402]  104.2 60.22 180 top
R10937  *10k_4  [R0402]  148.06 55.7 270 top
R10938  1k/f_4  [R0402]  116.72 59.71 0 top
R10939  240_4  [R0402]  110.04 67.08 0 top
R10940  10k_4  [R0402]  149.03 55.7 90 top
R10941  240_4  [R0402]  104.45 55.52 180 top
R10942  240_4  [R0402]  104.45 53.49 180 top
R10943  10k_4  [R0402]  147.83 57.86 90 top
R11043  *0_4  [R0402]  110.72 101.32 270 top
R11044  *0_4  [R0402]  114.97 108.2 270 top
R11047  *0_4  [R0402]  204.53 49.12 180 bottom
R11061  *short_4  [S0402]  165.03 105.81 270 bottom
R11062  *short_4  [S0402]  164.01 105.81 270 bottom
R11064  100k_4  [R0402]  24.95 53.87 270 top
R11107  for17@33_4  [R0402]  171.1 23.9 270 bottom
R11108  *short_4  [S0402]  214.19 107.83 180 bottom
R11110  *short_4  [S0402]  162.11 93.21 90 bottom
R11111  *short_4  [S0402]  153.6 94.89 0 top
R11112  *short_4  [S0402]  117.28 127.4 90 bottom
R11113  *short_4  [S0402]  116.39 127.4 90 bottom
R11114  10k_4  [R0402]  154.77 71.98 180 top
R11118  0_4  [R0402]  176.26 47.87 270 bottom
R11119  *0_4  [R0402]  176.46 45.94 180 bottom
R11126  *0_6  [R0603]  177.58 55.11 0 top
R11127  0_6  [R0603]  177.58 53.72 0 top
R11129  *short_4  [S0402]  78.67 9.8 90 top
R11131  *short_6  [S0603]  144.84 116.99 180 bottom
R11133  *short_4  [S0402]  148.65 53.41 180 top
R11134  *short_4  [S0402]  155.38 63.39 180 top
R11136  *short_4  [S0402]  39.43 25.55 180 top
R11137  *short_4  [S0402]  42.22 25.55 180 top
R11138  *short_4  [S0402]  44.76 25.55 180 top
R11139  *short_4  [S0402]  26.73 25.04 90 top
R11140  *short_4  [S0402]  158.5 71.39 180 top
R11141  *short_4  [S0402]  32.82 24.66 180 top
R11142  *0_4  [R0402]  155.58 60.42 180 top
R11153  *short_4  [S0402]  37.34 111.14 0 top
R11170  *0_4  [R0402]  155.35 56.33 180 top
R11175  *for15@0_4  [R0402]  200.84 49.12 0 bottom
R11176  *for15@0_4  [R0402]  200.84 48.2 0 bottom
R11179  *for17@0_4  [R0402]  202.62 47.19 0 bottom
R11180  *for17@0_4  [R0402]  201.43 50.08 0 bottom
R11181  *for15@0_4  [R0402]  202.63 48.1 180 bottom
R11182  *for15@0_4  [R0402]  202.63 49.12 180 bottom
R11185  *short_4  [S0402]  206.38 47.95 0 bottom
R11186  *short_4  [S0402]  206.38 49.12 0 bottom
R11187  4.7k_4  [R0402]  26.35 72.41 270 top
R11188  4.7k_4  [R0402]  25.46 72.41 270 top
R11189  *0_4  [R0402]  24.57 63.9 90 top
R11190  *0_4  [R0402]  23.55 63.9 90 top
R11191  *short_4  [S0402]  19.23 68.35 180 top
R11192  *short_4  [S0402]  19.23 69.49 180 top
R11193  *typec@100k/f_4  [R0402]  32.31 104.41 270 top
R11194  typec@100k/f_4  [R0402]  29.65 104.41 270 top
R11195  typec@100k/1%_4  [R0402]  19.49 110.51 270 top
R11196  *short_4  [S0402]  15.78 118.79 0 bottom
R11197  typec@100k/f_4  [R0402]  30.54 104.41 270 top
R11198  typec@100k/f_4  [R0402]  35.49 112.29 0 top
R11199  *short_4  [S0402]  15.78 119.55 0 bottom
R11200  typec@10k/5%_4  [R0402]  18.34 112.54 270 top
R11201  typec@10k/5%_4  [R0402]  25.71 102.38 180 top
R11202  *short_4  [S0402]  15.78 120.49 0 bottom
R11203  typec@100k/f_4  [R0402]  31.43 104.41 270 top
R11204  typec@100k/1%_4  [R0402]  31.53 111.7 180 top
R11205  typec@100k/f_4  [R0402]  35.49 111.14 0 top
R11206  typec@100k/f_4  [R0402]  34.12 104.41 270 top
R11207  *short_4  [S0402]  15.78 121.3 0 bottom
R11208  typec@100k/f_4  [R0402]  33.2 104.41 270 top
R11209  *typec@4.7k/f_4  [R0402]  27.79 121.09 0 bottom
R11210  *typec@4.99k/f_4  [R0402]  31.68 114.19 90 top
R11211  *typec@0_4  [R0402]  32.57 114.19 270 top
R11212  *typec@0_4  [R0402]  30.79 124.61 90 top
R11213  *typec@0_4  [R0402]  30.79 114.19 270 top
R11214  *typec@0_4  [R0402]  29.9 124.61 90 top
R11251  20k/f_4  [R0402]  31.35 102 90 top
R11252  *short_4  [S0402]  29.65 102 90 top
R11253  *short_4  [S0402]  30.92 25.55 0 top
R11254  *short_4  [S0402]  29.01 25.55 0 top
R11255  *short_4  [S0402]  32.77 26.44 180 top
R11256  *short_4  [S0402]  27.62 25.04 90 top
R11257  *short_6  [S0603]  31.6 73.45 90 top
R11258  *short_4  [S0402]  39.05 65.42 90 top
R11259  *short_4  [S0402]  38.16 67.33 90 top
R11260  *ioac@0_4  [R0402]  35.24 64.15 270 top
R11261  nac@0_4  [R0402]  34.22 64.15 270 top
R11262  15k_4  [R0402]  37.22 64.15 90 top
R11263  1k_4  [R0402]  38.03 61.74 270 top
R11264  2.49k_4  [R0402]  42.22 78.12 90 top
R11265  75/f_8  [R0805]  24.44 85.49 0 top
R11266  *short_8  [S0805]  41.89 65.04 90 top
R11267  *short_4  [S0402]  15.3 88.56 270 bottom
R11268  47/f_4  [R0402]  13.39 80.46 0 top
R11269  *33_4  [R0402]  14.05 84.42 90 top
R11270  *short_4  [S0402]  9.84 87.27 270 bottom
R11271  47/f_4  [R0402]  13.39 82.47 0 top
R11272  *33_4  [R0402]  9.43 84.73 90 top
R11273  12.4k/f_4  [R0402]  19.39 53.36 270 top
R11274  *10k_4  [R0402]  16.52 53.36 270 top
R11275  10k_4  [R0402]  21.39 53.36 270 top
R11276  *0_4  [R0402]  20.53 53.36 270 top
R11277  0_4  [R0402]  15.55 53.36 270 top
R11278  typec@10k/5%_4  [R0402]  37.24 112.82 270 top
R11279  *0_4  [R0402]  136.79 74.95 90 top
R11280  *short_4  [S0402]  35.49 113.81 180 top
R11281  *short_4  [S0402]  34.09 102.51 270 top
R11282  *0_4  [R0402]  218.67 89.38 90 bottom
R11283  10k_4  [R0402]  171.33 110.79 90 bottom
R11284  *short_4  [S0402]  173.66 84.44 180 bottom
R11285  *4.7k_4  [R0402]  22.92 73.55 270 top
R11286  4.7k_4  [R0402]  21.9 73.55 270 top
R11287  *4.7k_4  [R0402]  24.36 73.55 270 top
R11288  fpd@0_4  [R0402]  109.91 34.56 0 top
R11289  *fpd@0_4  [R0402]  109.91 35.58 0 top
R11290  *fpd@0_4  [R0402]  110.29 33.17 90 top
R11291  *fpd_sp@0_4  [R0402]  116.11 24.96 270 bottom
R11293  fpd@0_4  [R0402]  110.67 18.94 270 bottom
R11294  fpd@0_4  [R0402]  109.53 18.94 270 bottom
R11295  fpd@0_4  [R0402]  108.39 18.94 270 bottom
R11296  fpd@0_4  [R0402]  107.24 18.94 270 bottom
R11297  fpd@10k_4  [R0402]  117.2 30.2 0 top
R11298  *short_4  [S0402]  115.35 30.2 0 top
R11299  fpd_sp@0_4  [R0402]  114.84 25.72 90 bottom
R11300  fpd_sp@0_4  [R0402]  116.11 25.72 90 bottom
R11301  *fpd_sp@0_4  [R0402]  114.84 24.96 270 bottom
R11302  fpd_sp@0_4  [R0402]  114.84 20.14 90 bottom
R11303  *fpd_sp@0_4  [R0402]  114.84 20.9 270 bottom
R11304  fpd_sp@0_4  [R0402]  116.11 20.14 90 bottom
R11305  *fpd_sp@0_4  [R0402]  116.11 20.9 270 bottom
RP1  10k_10p8r  [10P8R]  195.2 27.39 270 bottom
SW1  bi_sw  [SW-TMG-533-TR-6P]  231 121.9 180 bottom
SW2  *power_sw  [SW-TMG-533-TR-6P]  219.64 31.64 0 bottom
SW4  lid switch  [SW-DS-A40E-4P]  216 92.4 180 bottom
TP12  *  [TP2650]  121.19 118.49 0 top
TP14  *  [TP2650]  127.31 105.68 0 top
TP17  *  [TP2650]  126.45 107.92 0 top
TP19  *  [TP2675]  158.02 101.11 270 top
TP20  *  [TP2650]  122.89 108.07 0 top
TP22  *  [TP2650]  146.11 100.98 180 bottom
TP23  *  [TP2675]  133.79 96.92 180 bottom
TP29  *  [TP2675]  152.03 100.63 0 top
TP30  *  [TP2675]  133.56 102.94 0 top
TP31  *  [TP2675]  135.31 100.73 0 top
TP34  *  [TP2650]  200.54 35.58 0 bottom
TP44  *  [TP2675]  47.5 71.8 0 top
TP62  *  [TP2650]  107.27 128.42 180 bottom
TP63  *  [TP2675]  144.68 124.56 180 bottom
TP64  *  [TP2650]  109.25 128.19 180 bottom
TP65  *  [TP2650]  102.52 127.55 180 bottom
TP74  *  [TP2675]  159.75 72.77 0 top
TP75  *  [TP2650]  9.84 73.68 0 top
TP76  *  [TP2675]  203.21 171.16 0 top
TP77  *  [TP2650]  184.56 46.86 90 bottom
TP84  *  [TP2675]  129.24 103.63 0 top
TP88  *  [TP2675]  109.45 107.89 0 top
TP89  *  [TP2650]  108.11 131.06 180 bottom
TP90  *  [TP2650]  109.15 130.3 180 bottom
TP91  *  [TP2650]  108.08 129.41 180 bottom
TP92  *  [TP2650]  103.94 127.55 180 bottom
TP93  *  [TP2650]  116.13 119.27 0 top
TP94  *  [TP2650]  116.77 120.67 0 top
TP95  *  [TP2675]  128.96 108.6 0 top
TP108  *  [TP2675]  173.01 94 180 bottom
TP109  *  [TP2675]  160.84 93.24 180 bottom
TP143  *pad  [TP2675]  14.38 115.79 0 top
TP144  *pad  [TP2675]  18.55 115.29 0 top
TP150  *  [TP2675]  158.93 93.24 180 bottom
TP153  *  [TP2650]  131.96 51.33 0 top
TP154  *  [TP2650]  124.14 40.53 0 top
TP157  *  [TP2650]  122.87 69.36 0 top
TP158  *  [TP2650]  131.76 52.6 0 top
TP4000  *  [TP2650]  184.71 125.8 0 top
TP4104  *  [TP2650]  189.97 128.82 0 top
TP4105  *  [TP2650]  190 134.54 0 top
TP4106  *  [TP2650]  185.15 140.23 0 top
TP4107  *  [TP2650]  177.25 142.11 0 top
TP4300  *  [TP2650]  162.49 121.69 180 bottom
TP4301  *  [TP2650]  164.55 126.03 180 bottom
TP4302  *  [TP2650]  186.39 115.36 180 bottom
TP4303  *  [TP2650]  163.63 127.3 180 bottom
TP4304  *  [TP2650]  187.32 123.31 0 top
TP4305  *  [TP2650]  165.39 128.29 180 bottom
TP4306  *  [TP2650]  185.48 120.54 0 top
TP4307  *  [TP2650]  163.76 124.48 180 bottom
TP4308  *  [TP2650]  184.71 123.21 0 top
TP4309  *  [TP2650]  185.65 124.81 0 top
TP4333  *  [TP2675]  45.27 71.14 0 top
TP4334  *  [TP2675]  42.22 69.77 0 top
TP4335  *  [TP2675]  48.06 69.82 0 top
TP4336  *  [TP2675]  46.49 68.7 0 top
TP4344  *  [TP2675]  96.35 100.83 180 bottom
TP4354  *  [TP2675]  146.06 110.76 180 bottom
TP4355  *  [TP2675]  147.68 111.81 180 bottom
TP4356  *  [TP2675]  150.32 111.81 180 bottom
TP4357  *  [TP2675]  144.07 111.6 180 bottom
TP4358  *  [TP2675]  166.17 65.83 90 bottom
TP4359  *  [TP2675]  167.24 64.13 90 bottom
TP4360  *  [TP2675]  169.83 69.82 90 bottom
TP4361  *  [TP2675]  170.39 71.65 90 bottom
TP4362  *  [TP2650]  196.53 58.82 180 bottom
TP4363  *  [TP2650]  195.81 57.65 180 bottom
TP4366  *  [TP2650]  150.5 187.9 0 top
TP4367  *  [TP2675]  156.32 87.22 180 bottom
TP4368  *  [TP2675]  153.98 100.63 0 top
TP4369  *  [TP2675]  154.74 86.1 180 bottom
TP4372  *  [TP2675]  148.65 116.99 180 bottom
TP4373  *  [TP2675]  144.66 122.65 180 bottom
TP4376  *  [TP2650]  23.3 72.03 0 top
TP4377  *  [TP2650]  143.74 106.14 0 top
TP4378  *  [TP2650]  143.06 107.72 0 top
TP4390  *  [TP2650]  139.27 116.78 0 top
TP4392  *  [TP2650]  111.18 131.08 0 top
TP4393  *  [TP2650]  111.82 132.23 0 top
TP4394  *  [TP2650]  109.76 128.14 0 top
TP4395  *  [TP2650]  110.65 129.69 0 top
TP4396  *  [TP2675]  117.79 22.88 0 bottom
TP4397  *  [TP2675]  171.05 94 180 bottom
TP4398  *  [TP2675]  158.91 106.88 0 top
TP4399  *  [TP2675]  117.79 20.97 0 bottom
U1  g5245at11u  [SOT23-2_8-95-6P]  110.42 159.4 0 bottom
U3  ev_b@gddr5  [BGA170-HYNIX-H5GQ1H24MJR]  212.98 123.2 0 bottom
U4  ev_b@gddr5  [BGA170-HYNIX-H5GQ1H24MJR]  213 143.45 180 bottom
U5  ev_a@gddr5  [BGA170-HYNIX-H5GQ1H24MJR]  194.15 161.42 90 bottom
U6  74aup1g07gw  [SOT353-1-2_125-65-5P]  84.89 124.73 90 bottom
U7  ev_a@gddr5  [BGA170-HYNIX-H5GQ1H24MJR]  173.98 161.39 270 bottom
U8  *tc7sh08fu  [SSOP5-P-A-TOSHIBA-B]  182.68 35.96 0 top
U9  typec@ptn36242lbs  [TQFN32-3X6-4-41P-0_8H]  30.41 119.4 90 top
U12  g991p11u  [SOIC8-6-1_27]  71.37 117.1 90 bottom
U13  rl6420_32pin  [QFN32-4X4-4-33P-0_9H]  23.68 68.35 90 top
U14  tc7sh08fu  [SSOP5-P-A-TOSHIBA-B]  162.64 86.13 180 bottom
U15  rtl8411b-cg  [QFN48-6X6-4-49P-ALC280]  37.9 72.66 180 top
U16  *for17@kmm40301026-18ds  [MIC-KMM40301026-11DN-8P]  133 84.4 90 top
U17  kmm40301026-18ds  [MIC-KMM40301026-11DN-8P]  82.99 84.4 90 top
U18  ptn3366bs  [QFN32-5X5-5-37P-0_85H]  18.98 48.28 180 top
U19  *gs@lis3dhtr  [LGA16-3X3-5]  220.02 57.04 0 bottom
U20  g524b2t11u  [SOT23-5]  21.9 37.99 270 top
U21  usb30_esd_az1065-06f.r7g  [ESD10-4_1X2-8-11P]  18.09 32.4 270 top
U22  tps2544rter  [QFN16-3X3-5-22P-TPS2544RTER]  18.27 26.49 180 top
U23  alc255  [QFN48-6X6-4-49P-ALC280]  204.4 32.4 0 bottom
U24  usb30_esd_az1065-06f.r7g  [ESD10-4_1X2-8-11P]  17.53 14.24 270 top
U25  *g923-330t1uf  [SOT23-5]  206.05 21.86 180 bottom
U28  typec@tps25810rvcr(qfn)  [QFN20-4X3-5-27P]  32.06 108.6 90 top
U33  *74aup1g07gw  [SOT353-1-2_125-65-5P]  101.12 139.29 90 bottom
U35  sp@skl_ult/bga  [BGA1356-INTEL-SKYLAKE-U]  120.5 112.4 270 bottom
U36  *rclamp0524p  [SLP10-2_5X1-5-10P]  10.34 81.05 90 top
U37  *m74vhc1gt125df2g  [SSOP5-P-A-TOSHIBA-B]  10.47 87.52 90 top
U38  *rclamp0524p  [SLP10-2_5X1-5-10P]  10.34 75.97 90 top
U40  *m74vhc1gt125df2g  [SSOP5-P-A-TOSHIBA-B]  13.39 87.65 90 top
U41  w25q64fv  -- 8mb  [SOIC8-8-1_27]  180.27 53.99 0 bottom
U42  transformer  [TRF-N1010G-25P]  28.5 82.9 270 bottom
U43  *74aup1g07gw  [SOT353-1-2_125-65-5P]  201.86 183.92 0 bottom
U44  *tpm@npct620/650_qfn32  [QFN32-5X5-5-33P-0_85H]  165.87 72.21 180 bottom
U45  it8987/cx  [LQFP128-16X16-4-1_6H]  179.38 35.2 270 bottom
U47  tc7sh08fu  [SSOP5-P-A-TOSHIBA-B]  87.56 124.73 90 bottom
U48  *tc7sh08fu  [SSOP5-P-A-TOSHIBA-B]  174.5 52.39 270 bottom
U49  *tc7sh08fu  [SSOP5-P-A-TOSHIBA-B]  194.44 35.45 180 bottom
U50  *tc7sh08fu  [SSOP5-P-A-TOSHIBA-B]  157.61 32.94 270 bottom
U1006  *fpd@pi3usb102  [TQFN10-1_6X1_3-4-SMT]  115.47 22.93 0 bottom
U3002  ev_sp@n16  [BGA908-NVIDIA-N13P-GS-A1]  182.23 132.44 180 bottom
U4001  gc6@74ahc1g09gw  [SSOP5-P-A-TOSHIBA-B]  211.27 107.2 180 bottom
U4002  gc6@tc7sh08fu(f)  [SSOP5-P-A-TOSHIBA-B]  217.11 106.69 180 bottom
U4509  typec@az1043-08f  [ESD-3_8X1-9P]  13.47 119.78 90 bottom
U4511  g524b2t11u  [SOT23-5]  214.23 32.99 180 bottom
U4512  *for15@kmm40301026-18ds  [MIC-KMM40301026-11DN-8P]  170.49 84.4 90 top
U4513  typec@az1045-08f  [ESD-3_8X1-9P]  15.93 116.4 270 top
Y1  25mhz  [XTL-3_2X2_5-2_2X1_7]  45.52 73.96 90 top
Y2  32.768khz  [XTL-3_2X1_5-2_5-0_8H]  156.01 106.57 270 bottom
Y4  24mhz  [XTL-3_2X2_5-2_2X1_7-4P]  116.64 134 0 bottom
Y4200  ev@27mhz_10  [XTL-3_2X2_5-2_2X1_7]  193.66 112.19 180 bottom

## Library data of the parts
BT1 = BAT-AP-AAA-BAT-054-K01-2P-SMT
C2 C4 C8-C10 C12 C13 C16 C19 C27 C33-C35 C41 C114 C136 C148 C151 C155 C157 C158 C161 C164 C165 C168 C170 C172-C174 C176 C179 C181 C184-C186 C188 C189 C191-C195 C197 C198 C200 C201 C204-C207 C209 C212 C214-C218 C221-C223 C225 C227-C230 C232 C237-C242 C244 C246 C247 C249 C250 C252 C254 C256-C268 C270 C278-C281 C283 C284 C286 C288 C290-C292 C297-C301 C304 C305 C308 C311-C320 C322-C339 C341 C343-C346 C348-C357 C360 C362-C365 C367-C371 C373 C374 C376-C383 C386 C387 C389 C394 C398 C405-C408 C411 C413 C424 C425 C428 C431 C435-C437 C450 C451 C453 C454 C456 C458-C462 C469 C475-C477 C481-C485 C488-C502 C504 C505 C507-C511 C513 C514 C517-C520 C522 C524-C530 C532 C534-C538 C541 C545-C548 C550 C551 C553-C555 C577 C578 C580 C581 C628 C641-C643 C647-C649 C651-C658 C660-C665 C667-C669 C672-C689 C695 C698 C700 C701 C708-C714 C716 C718-C721 C724 C726 C728 C730-C733 C735 C739 C742-C744 C747-C751 C753-C764 C766 C768 C770-C772 C774 C775 C777 C778 C780 C781 C783 C785-C788 C793 C794 C796-C808 C811-C819 C821-C824 C963 C1164 C1166-C1169 C1176 C1177 C1211 C1244 C1245 C1249 C1251-C1254 C1256 C1258-C1261 C1266 C1267 C1271 C1273 C1275 C1309-C1311 C1314 C1315 C1317-C1320 C1323 C1325 C1329 C1332 C1333 C1335-C1337 C1377 C1386 C1388 C1391 C1394 C1396 C1398 C1401-C1403 C1409 C1413-C1416 C1418-C1423 C1432 C1435 C1436 C1438-C1440 C1448 C1450 C1457 C1458 C1497-C1499 C1504 C1513 C1537 C1538 C1543 C1544 C1549 C1551 C1764 C3000 C3002 C3007 C3008 C3224-C3227 C4008-C4011 C4013 C4015-C4041 C4100-C4110 C4112 C4113 C4200-C4203 C4205-C4207 C4209-C4211 C4400-C4407 C4596 C4598 C4599 C4601-C4609 C4611-C4617 C4664 C4665 C4713-C4715 C4723 C4726-C4728 C4733-C4737 C4748-C4752 C4762-C4764 C4767 C4768 C4770 C4771 C4773 C4774 C4776-C4787 C4793-C4822 D2-D6 D24-D27 D4013 D4014 EC35-EC50 PC1 PC3 PC6-PC12 PC14-PC46 PC55-PC58 PC75 PC79 PC81 PC83-PC85 PC87-PC92 PC98 PC100 PC101 PC103 PC106-PC114 PC123 PC125 PC129-PC135 PC137 PC139 PC159-PC161 PC171 PC175-PC178 PC180 PC184 PC185 PC187 PC189 PC191 PC193 PC195 PC196 PC199 PC200 PC203 PC206 PC209 PC210 PC212 PC214 PC215 PC217 PC218 PC221 PC226 PC227 PC229 PC230 PC235 PC240 PC241 PC246 PC247 PC250 PC252 PC269 PC271 PC272 PC274 PC283 PC285-PC287 PC291-PC293 PC300 PC301 PC303 PC304 PC6100 PC6214 PC6218 PC6228 = C0402
C7 C29 C30 C144 C150 C182 C190 C199 C248 C645 C650 C659 C666 C690 C696 C697 C699 C702 C4711 PC47 PC49 PC52 PC54 PC86 PC99 PC118 PC120 PC127 PC148 PC152 PC155 PC157 PC164-PC170 PC172 PC181 PC190 PC192 PC194 PC205 PC211 PC213 PC216 PC219 PC220 PC228 PC238 PC254 PC277 PC6216 PC6220 PC6232 PC6233 = C0805
C73 C457 C740 C1162 C4435 C4772 = C3528
C169 C171 C178 C187 C202 C203 C210 C219 C224 C226 C233 C236 C243 C251 C255 C272-C277 C282 C289 C302 C303 C307 C310 C321 C340 C347 C366 C412 C438 C515 C516 C523 C549 C552 C556 C691-C694 C703-C707 C723 C737 C752 C765 C767 C776 C790 C965 C1163 C1165 C1212 C1246-C1248 C1250 C1255 C1257 C1262-C1265 C1270 C1272 C1308 C1312 C1313 C1321 C1324 C1327 C1328 C1330 C1331 C1334 C1399 C1408 C1447 C3001 C4000-C4007 C4012 C4014 C4111 C4115 C4117 C4119 C4204 C4208 C4408-C4434 C4597 C4600 C4618 C4647-C4650 C4753 C4754 C4765 C4766 C4769 C4775 C4788 D23 D28 D34 D4002 PC2 PC4 PC5 PC13 PC48 PC50 PC51 PC53 PC61 PC65 PC70 PC71 PC74 PC76-PC78 PC80 PC97 PC102 PC104 PC105 PC115-PC117 PC119 PC121 PC122 PC124 PC126 PC128 PC136 PC140-PC147 PC149-PC151 PC153 PC154 PC156 PC173 PC174 PC179 PC182 PC183 PC188 PC197 PC198 PC202 PC207 PC208 PC222 PC223 PC225 PC231-PC234 PC236 PC237 PC239 PC242-PC245 PC248 PC249 PC251 PC253 PC267 PC268 PC270 PC273 PC275 PC276 PC278-PC282 PC288-PC290 PC302 PC6098 PC6213 PC6215 PC6219 PC6221 PC6222 PC6225 PC6226 PC6230 PC6231 = C0603
C196 C235 C245 C269 C285 = C0201
C452 C487 C4712 = C1206
C746 = CC1808
CN2 = 88511-180N-18P-L
CN4 = SDCARD-PSDAT4-11GLBS1NN4H4-11P
CN5 = GS12401-1011-40P-R-NH-SMT
CN6 = 50591-00401-001-4P-L
CN7 = DSUB-95-0005-01-15P
CN8 = HS8803F-3P-L
CN9 = SATA-C185Q2-11311-L-13P-R
CN10 = NGFF-NASE0-S6701-TS48-KE-SMT
CN11 = RJ45-JM361C-HP34AA03-9H-8P
CN12 = HDMI-10444-19001-19P
CN13 CN16 = UB3-YUSB0021-P001A-9P-SMT
CN14 = SATA-C166FQ-12208-L-22P-R
CN17 = 50503-0080N-001-8P-L
CN18 = 50271-0040N-V01-4P-L
CN20 CN2019 = 196153-28021-35-28P-L
CN23 = NGFF-NASM0-S6701-TS50-KM-SMT
CN95 = 196241-08021-3-8P-L
CN2020 = 51619-0260N-001-26P-L
CN2021 = UB31-DX07B024XJ1AR1000-24P-SMT
D1 D8-D11 D14-D18 D20 D30 D31 D35 D4001 D4012 PD1 PD2 PD4 = DSM
D7 = SOT323_213-2_1-1_3-2N7002W
D12 = DSMV
D4000 PQ6 PQ11 PQ13 Q4 Q19 Q27 Q35 Q76 Q4002 Q4200 Q4202 = UMT_213-3-1_3
EC51-EC54 = ESD-1X0_6-2P
HOLE1-HOLE4 = HG-C354D134P2
HOLE6 HOLE7 = HG-TC354IC236BC236D118P2
HOLE8 = H-C236I156D140P2
HOLE9 = H-C236D140P2
HOLE10-HOLE12 = H-TC236IC236BC256D161P2
HOLE13-HOLE15 = H-C256D161P2
HOLE16 = H-TC217BC197D126P2
HOLE17 HOLE18 = H-ZAB-2
HOLE19 = H-ZAB-5
HOLE20 = H-C87D87N
HOLE21 = H-O146X87D146X87N
HOLE22 = O-ZAA-1
HOLE23 HOLE24 = HG-C315D134P2
HOLE26 = H-C217D217N
J1 = JOPEN25X30_S
JDIM1 = DDR4-D4AS0-26001-1P52-STD-SMT
JDIM2 = DDR4-D4AR0-26001-1P52-RVS-SMT
